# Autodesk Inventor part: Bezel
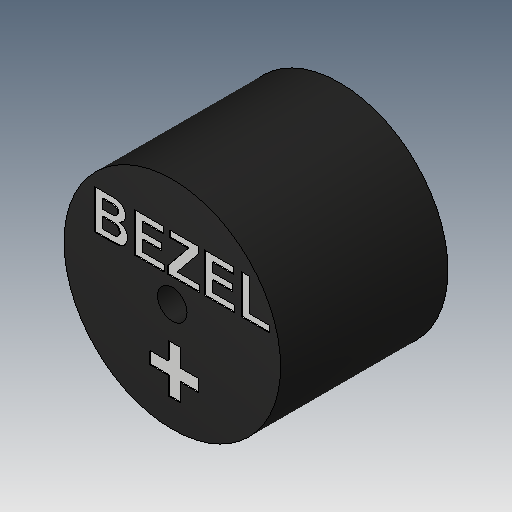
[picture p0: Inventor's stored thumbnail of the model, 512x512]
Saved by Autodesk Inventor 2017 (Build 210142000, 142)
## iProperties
Created: 2005-12
Part Number: Bezel
Material: Generic
Document SubType Name: Modeling
Designer: DanielSeverino
Density: 1 g/cm^3
Appearance: Default
Author: DanielSeverino
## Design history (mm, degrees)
feature "Solid1"
body "Solid2"
